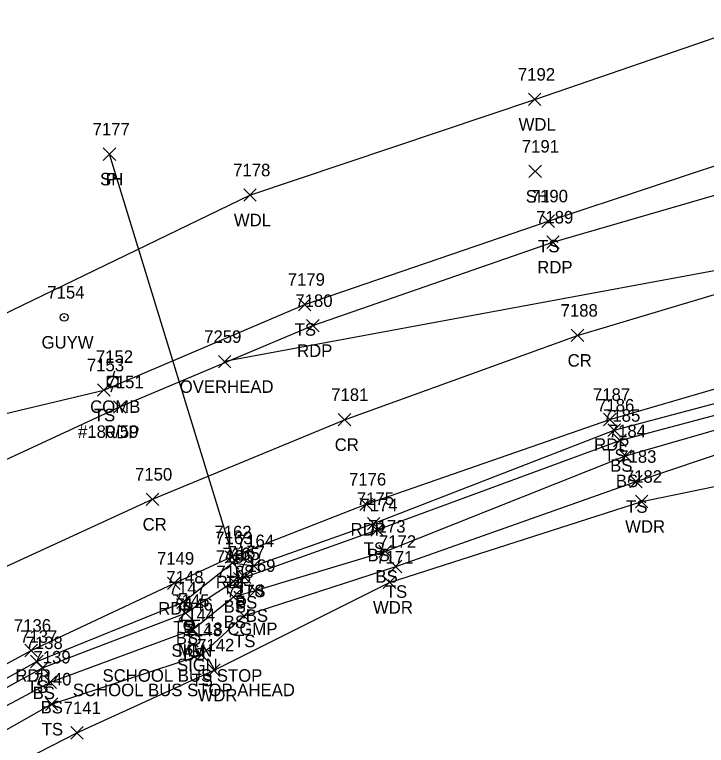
# Model space of a CAD drawing. Extents: x 1611797 to 1633212, y 298978 to 305475.
# Drawn here: x 1624387.7 to 1624498.3, y 304428 to 304544.9 of the extents above; entities that cross this region are included whole.
import ezdxf

# ---------------------------------------------------------------- set-up
doc = ezdxf.new("R2010")
doc.units = 0
for name, color, linetype in [('D_A', 7, 'Continuous'), ('D_C', 7, 'Continuous'), ('D_I', 7, 'Continuous'), ('D_TIC', 7, 'Continuous'), ('DCP', 7, 'Continuous'), ('L_A', 7, 'Continuous'), ('L_I', 7, 'Continuous'), ('L_TIC', 7, 'Continuous'), ('LAWA', 7, 'Continuous'), ('LELB', 7, 'Continuous'), ('P_A', 7, 'Continuous'), ('P_I', 7, 'Continuous'), ('P_TIC', 7, 'Continuous'), ('PET', 7, 'Continuous'), ('PRC', 7, 'Continuous'), ('S_A', 7, 'Continuous'), ('S_C', 7, 'Continuous'), ('S_I', 7, 'Continuous'), ('SRM', 7, 'Continuous'), ('SSGN', 7, 'Continuous'), ('U_A', 7, 'Continuous'), ('U_C', 7, 'Continuous'), ('U_I', 7, 'Continuous'), ('U_TIC', 7, 'Continuous'), ('UCO', 7, 'Continuous'), ('UP', 7, 'Continuous'), ('UPGW', 7, 'Continuous')]:
    doc.layers.add(name, color=color, linetype=linetype)

msp = doc.modelspace()

# ---------------------------------------------------------------- linework, layer by layer
at = {"layer": 'D_TIC'}
for points in [[(1624401.83, 304521.56), (1624403.83, 304523.56)], [(1624403.83, 304521.56), (1624401.83, 304523.56)], [(1624422.66, 304453.61), (1624424.66, 304455.61)], [(1624424.66, 304453.61), (1624422.66, 304455.61)]]:
    msp.add_lwpolyline(points, dxfattribs=at)
at = {"layer": 'DCP'}
msp.add_lwpolyline([(1624423.66, 304454.61), (1624402.83, 304522.56)], dxfattribs=at)
at = {"layer": 'L_TIC'}
for points in [[(1624469.84, 304530.32), (1624471.84, 304532.32)], [(1624471.84, 304530.32), (1624469.84, 304532.32)], [(1624401.83, 304521.56), (1624403.83, 304523.56)], [(1624403.83, 304521.56), (1624401.83, 304523.56)], [(1624469.9, 304518.8), (1624471.9, 304520.8)], [(1624471.9, 304518.8), (1624469.9, 304520.8)], [(1624424.3, 304515.01), (1624426.3, 304517.01)], [(1624426.3, 304515.01), (1624424.3, 304517.01)], [(1624471.98, 304510.84), (1624473.98, 304512.84)], [(1624473.98, 304510.84), (1624471.98, 304512.84)], [(1624433.05, 304497.5), (1624435.05, 304499.5)], [(1624435.05, 304497.5), (1624433.05, 304499.5)], [(1624400.92, 304483.81), (1624402.92, 304485.81)], [(1624402.92, 304483.81), (1624400.92, 304485.81)], [(1624482.55, 304477.38), (1624484.55, 304479.38)], [(1624484.55, 304477.38), (1624482.55, 304479.38)], [(1624483.46, 304475.74), (1624485.46, 304477.74)], [(1624485.46, 304475.74), (1624483.46, 304477.74)], [(1624484.37, 304473.27), (1624486.37, 304475.27)], [(1624486.37, 304473.27), (1624484.37, 304475.27)], [(1624486.04, 304469.17), (1624488.04, 304471.17)], [(1624488.04, 304469.17), (1624486.04, 304471.17)], [(1624486.94, 304465.98), (1624488.94, 304467.98)], [(1624488.94, 304465.98), (1624486.94, 304467.98)], [(1624444.07, 304462.44), (1624446.07, 304464.44)], [(1624446.07, 304462.44), (1624444.07, 304464.44)], [(1624444.65, 304461.42), (1624446.65, 304463.42)], [(1624446.65, 304461.42), (1624444.65, 304463.42)], [(1624445.91, 304458), (1624447.91, 304460)], [(1624447.91, 304458), (1624445.91, 304460)], [(1624421.5, 304456.15), (1624423.5, 304458.15)], [(1624423.5, 304456.15), (1624421.5, 304458.15)], [(1624424.95, 304455.68), (1624426.95, 304457.68)], [(1624426.95, 304455.68), (1624424.95, 304457.68)], [(1624447.61, 304455.57), (1624449.61, 304457.57)], [(1624449.61, 304455.57), (1624447.61, 304457.57)], [(1624423.46, 304453.85), (1624425.46, 304455.85)], [(1624425.46, 304453.85), (1624423.46, 304455.85)], [(1624421.64, 304453.19), (1624423.64, 304455.19)], [(1624423.64, 304453.19), (1624421.64, 304455.19)], [(1624446.61, 304453.04), (1624448.61, 304455.04)], [(1624448.61, 304453.04), (1624446.61, 304455.04)], [(1624425.18, 304451.72), (1624427.18, 304453.72)], [(1624427.18, 304451.72), (1624425.18, 304453.72)], [(1624413.63, 304449.88), (1624415.63, 304451.88)], [(1624415.63, 304449.88), (1624413.63, 304451.88)], [(1624421.67, 304450.72), (1624423.67, 304452.72)], [(1624423.67, 304450.72), (1624421.67, 304452.72)], [(1624414, 304448.13), (1624416, 304450.13)], [(1624416, 304448.13), (1624414, 304450.13)], [(1624423.34, 304447.67), (1624425.34, 304449.67)], [(1624425.34, 304447.67), (1624423.34, 304449.67)], [(1624415.16, 304445.51), (1624417.16, 304447.51)], [(1624417.16, 304445.51), (1624415.16, 304447.51)], [(1624390.23, 304440.37), (1624392.23, 304442.37)], [(1624392.23, 304440.37), (1624390.23, 304442.37)], [(1624416.55, 304441.42), (1624418.55, 304443.42)], [(1624418.55, 304441.42), (1624416.55, 304443.42)], [(1624391.11, 304439.37), (1624393.11, 304441.37)], [(1624393.11, 304439.37), (1624391.11, 304441.37)], [(1624418.55, 304439), (1624420.55, 304441)], [(1624420.55, 304439), (1624418.55, 304441)], [(1624392.38, 304437.07), (1624394.38, 304439.07)], [(1624394.38, 304437.07), (1624392.38, 304439.07)], [(1624392.58, 304433.55), (1624394.58, 304435.55)], [(1624394.58, 304433.55), (1624392.58, 304435.55)], [(1624396.63, 304428.96), (1624398.63, 304430.96)], [(1624398.63, 304428.96), (1624396.63, 304430.96)]]:
    msp.add_lwpolyline(points, dxfattribs=at)
at = {"layer": 'LAWA'}
for points in [[(1624088.25, 304303.5), (1624106.81, 304320.98), (1624153.79, 304356.6), (1624200.5, 304392.1), (1624247.6, 304427), (1624285.25, 304446.91), (1624325.08, 304470.25), (1624369.06, 304488.79), (1624425.3, 304516.01), (1624470.84, 304531.32), (1624503.11, 304542.37)], [(1624186.93, 304294.55), (1624240.75, 304330.36), (1624281.9, 304359.85), (1624320.17, 304387.37), (1624354.03, 304407.62), (1624397.63, 304429.96), (1624419.55, 304440), (1624447.61, 304454.04), (1624487.94, 304466.98), (1624522.27, 304474.07), (1624560.79, 304484.56), (1624594.39, 304487.85), (1624625.21, 304492.09), (1624656.2, 304492.85), (1624695.81, 304490.79), (1624736.39, 304487.29), (1624770.57, 304478.97), (1624808.86, 304473.48), (1624838.37, 304462.56)]]:
    msp.add_lwpolyline(points, dxfattribs=at)
at = {"layer": 'LELB'}
for points in [[(1624095.54, 304298.86), (1624107.13, 304308.7), (1624163.15, 304341.2), (1624211.36, 304376.85), (1624256.11, 304405.01), (1624295.12, 304429.63), (1624332.27, 304455.09), (1624374.78, 304478.34), (1624401.92, 304484.81), (1624434.05, 304498.5), (1624472.98, 304511.84), (1624506.38, 304522.93), (1624552.27, 304533.91), (1624584.91, 304535.68), (1624625.23, 304538.42), (1624653.95, 304544.88), (1624697.41, 304542.2), (1624744.04, 304535.67), (1624782.56, 304529.52), (1624820.4, 304520.29), (1624849.23, 304510.65), (1624882.95, 304501.96), (1624884.04, 304505.26)], [(1624181.13, 304309.78), (1624231.77, 304345.18), (1624273.89, 304372.63), (1624313.92, 304397.95), (1624349.41, 304418.31), (1624391.23, 304441.37), (1624414.63, 304450.88), (1624422.5, 304457.15), (1624425.95, 304456.68), (1624445.07, 304463.44), (1624483.55, 304478.38), (1624517.08, 304487.27), (1624559.27, 304496.93), (1624591.53, 304501.1), (1624624.74, 304505.99)], [(1624181.83, 304308.22), (1624233.12, 304343.37), (1624274.63, 304371.3), (1624314.75, 304397.03), (1624350.32, 304417.49), (1624392.11, 304440.37), (1624415, 304449.13), (1624422.64, 304454.19), (1624424.46, 304454.85), (1624445.65, 304462.42), (1624484.46, 304476.74), (1624518.06, 304485.67), (1624537.67, 304490.32), (1624539.56, 304490.64), (1624559.82, 304495.18), (1624592.05, 304499.97), (1624624.64, 304503.4)], [(1624183.73, 304304.83), (1624234.53, 304340.54), (1624276.44, 304368.9), (1624316.24, 304394.62), (1624351.26, 304415.55), (1624393.38, 304438.07), (1624416.16, 304446.51), (1624422.67, 304451.72), (1624426.18, 304452.72), (1624446.91, 304459), (1624485.37, 304474.27), (1624518.27, 304483.79), (1624538.49, 304488.99), (1624540.45, 304488.77), (1624560, 304493), (1624592, 304498.44), (1624624.83, 304501.63)], [(1624184.93, 304301.87), (1624278.34, 304363.53), (1624318.33, 304391.37), (1624353.31, 304411.71), (1624393.58, 304434.55), (1624417.55, 304442.42), (1624424.34, 304448.67), (1624448.61, 304456.57), (1624487.04, 304470.17), (1624519.68, 304481.19), (1624560.46, 304490.23), (1624593.88, 304492.76), (1624624.32, 304496.68), (1624656.79, 304498.13), (1624695.25, 304497.88), (1624738.57, 304491.31), (1624772.39, 304485.68), (1624810.08, 304476.48), (1624844.46, 304462.44), (1624886.48, 304449.94), (1624926.51, 304437.94), (1624967.18, 304426.7), (1624995.86, 304419.24)]]:
    msp.add_lwpolyline(points, dxfattribs=at)
at = {"layer": 'P_TIC'}
for points in [[(1624472.75, 304507.46), (1624474.75, 304509.46)], [(1624474.75, 304507.46), (1624472.75, 304509.46)], [(1624434.34, 304494.11), (1624436.34, 304496.11)], [(1624436.34, 304494.11), (1624434.34, 304496.11)], [(1624476.67, 304492.55), (1624478.67, 304494.55)], [(1624478.67, 304492.55), (1624476.67, 304494.55)], [(1624403.49, 304481.1), (1624405.49, 304483.1)], [(1624405.49, 304481.1), (1624403.49, 304483.1)], [(1624439.42, 304479.07), (1624441.42, 304481.07)], [(1624441.42, 304479.07), (1624439.42, 304481.07)], [(1624481.84, 304479.09), (1624483.84, 304481.09)], [(1624483.84, 304479.09), (1624481.84, 304481.09)], [(1624408.7, 304466.33), (1624410.7, 304468.33)], [(1624410.7, 304466.33), (1624408.7, 304468.33)], [(1624442.89, 304465.53), (1624444.89, 304467.53)], [(1624444.89, 304465.53), (1624442.89, 304467.53)], [(1624421.35, 304457.1), (1624423.35, 304459.1)], [(1624423.35, 304457.1), (1624421.35, 304459.1)], [(1624412.13, 304452.88), (1624414.13, 304454.88)], [(1624414.13, 304452.88), (1624412.13, 304454.88)], [(1624389.3, 304442.15), (1624391.3, 304444.15)], [(1624391.3, 304442.15), (1624389.3, 304444.15)]]:
    msp.add_lwpolyline(points, dxfattribs=at)
at = {"layer": 'PET'}
for points in [[(1624214.6, 304372.95), (1624258.69, 304401.17), (1624298.33, 304425.53), (1624336.86, 304448), (1624379.58, 304470.59), (1624404.49, 304482.1), (1624435.34, 304495.11), (1624473.75, 304508.46), (1624507.92, 304518.4), (1624553.76, 304528.58), (1624585.04, 304533.35), (1624625.18, 304536.71), (1624654.48, 304537.5), (1624696.33, 304535.75), (1624743.35, 304530.33), (1624780.81, 304524.04), (1624819.04, 304514.44), (1624851.35, 304505.26), (1624901.43, 304489.14), (1624942.08, 304475.33), (1624984.5, 304461.2), (1625019.22, 304449.6)], [(1624179.36, 304312.24), (1624229.96, 304347.62), (1624272.13, 304375.05), (1624312.98, 304399.89), (1624348.37, 304420.48), (1624390.3, 304443.15), (1624413.13, 304453.88), (1624422.35, 304458.1), (1624443.89, 304466.53), (1624482.84, 304480.09), (1624516.09, 304489.8), (1624559.13, 304499.19), (1624590.8, 304503.8), (1624624.98, 304507.12)]]:
    msp.add_lwpolyline(points, dxfattribs=at)
at = {"layer": 'PRC'}
msp.add_lwpolyline([(1624172.24, 304325.39), (1624222.29, 304360.15), (1624264.64, 304387.45), (1624305.78, 304412.86), (1624342.45, 304434.67), (1624384.5, 304455.76), (1624409.7, 304467.33), (1624440.42, 304480.07), (1624477.67, 304493.55), (1624512.04, 304503.84), (1624556.26, 304513.41), (1624588.6, 304518.56), (1624625.39, 304521.45), (1624654.72, 304521.97), (1624694.56, 304520.32), (1624741.33, 304515.35), (1624776.51, 304509.39), (1624814.64, 304500.05), (1624847.34, 304490.65), (1624897.27, 304475.63), (1624938.08, 304462.27), (1624974.99, 304449.94), (1625014.51, 304436.37)], dxfattribs=at)
at = {"layer": 'SRM'}
msp.add_lwpolyline([(1624414.95, 304447.76), (1624416.2, 304447.76), (1624416.2, 304446.51), (1624414.95, 304446.51)], close=True, dxfattribs=at)
msp.add_circle((1624415.57, 304447.14), 0.0833, dxfattribs=at)
at = {"layer": 'SSGN'}
for p, q in [((1624413.95, 304447.99), (1624417.28, 304447.99)), ((1624415.59, 304447.16), (1624415.59, 304447.16)), ((1624414.84, 304445.69), (1624418.17, 304445.69)), ((1624416.48, 304444.85), (1624416.48, 304444.85))]:
    msp.add_line(p, q, dxfattribs=at)
for centre in [(1624415.59, 304447.16), (1624416.48, 304444.85)]:
    msp.add_circle(centre, 0.833, dxfattribs=at)
at = {"layer": 'U_TIC'}
for points in [[(1624420.25, 304488.36), (1624422.25, 304490.36)], [(1624422.25, 304488.36), (1624420.25, 304490.36)]]:
    msp.add_lwpolyline(points, dxfattribs=at)
at = {"layer": 'UCO'}
msp.add_lwpolyline([(1624859.31, 304474.49), (1624700.84, 304542.82), (1624591.7, 304520.94), (1624421.25, 304489.36)], dxfattribs=at)
at = {"layer": 'UP'}
for p, q in [((1624402.52, 304485.33), (1624402.52, 304487)), ((1624402.52, 304487), (1624404.19, 304487)), ((1624403.61, 304487.83), (1624403.36, 304487)), ((1624404.19, 304487), (1624404.19, 304485.33)), ((1624403.36, 304486.16), (1624403.36, 304486.16)), ((1624404.19, 304485.33), (1624402.52, 304485.33)), ((1624403.11, 304484.5), (1624403.36, 304485.33))]:
    msp.add_line(p, q, dxfattribs=at)
msp.add_circle((1624403.36, 304486.16), 0.833, dxfattribs=at)
at = {"layer": 'UPGW'}
for radius in [0.625, 0.0833]:
    msp.add_circle((1624395.58, 304496.45), radius, dxfattribs=at)

# ---------------------------------------------------------------- texts
at = {"layer": 'D_A'}
for p in [(1624402.21, 304517.56), (1624423.04, 304449.61)]:
    msp.add_text('P', height=2, dxfattribs=at).set_placement(p)
at = {"layer": 'D_C'}
msp.add_text('18 CGMP', height=2, dxfattribs=at).set_placement((1624417.95, 304445.61))
at = {"layer": 'D_I'}
for s, p in [('7177', (1624400.14, 304525.56)), ('7165', (1624420.92, 304457.61))]:
    msp.add_text(s, height=2, dxfattribs=at).set_placement(p)
at = {"layer": 'L_A'}
for s, p in [('WDL', (1624468.26, 304526.32)), ('SH', (1624401.32, 304517.56)), ('SH', (1624469.39, 304514.8)), ('WDL', (1624422.72, 304511.01)), ('TS', (1624471.38, 304506.84)), ('TS', (1624432.45, 304493.5)), ('TS', (1624400.33, 304479.81)), ('TS', (1624481.96, 304473.38)), ('BS', (1624482.9, 304471.74)), ('BS', (1624483.81, 304469.27)), ('TS', (1624485.45, 304465.17)), ('WDR', (1624485.3, 304461.98)), ('TS', (1624443.48, 304458.44)), ('BS', (1624444.09, 304457.42)), ('BS', (1624445.36, 304454)), ('TS', (1624420.91, 304452.15)), ('TS', (1624424.36, 304451.68)), ('TS', (1624447.02, 304451.57)), ('BS', (1624422.9, 304449.85)), ('BS', (1624421.08, 304449.19)), ('WDR', (1624444.97, 304449.04)), ('BS', (1624424.62, 304447.72)), ('BS', (1624421.11, 304446.72)), ('TS', (1624413.03, 304445.88)), ('BS', (1624413.44, 304444.13)), ('TS', (1624422.75, 304443.67)), ('BS', (1624414.6, 304441.51)), ('TS', (1624415.96, 304437.42)), ('TS', (1624389.64, 304436.37)), ('BS', (1624390.55, 304435.37)), ('WDR', (1624416.91, 304435)), ('BS', (1624391.82, 304433.07)), ('TS', (1624391.99, 304429.55))]:
    msp.add_text(s, height=2, dxfattribs=at).set_placement(p)
at = {"layer": 'L_I'}
for s, p in [('7192', (1624468.15, 304534.32)), ('7177', (1624400.14, 304525.56)), ('7191', (1624468.77, 304522.8)), ('7178', (1624422.61, 304519.01)), ('7190', (1624470.2, 304514.84)), ('7179', (1624431.34, 304501.5)), ('7153', (1624399.22, 304487.81)), ('7186', (1624480.81, 304481.38)), ('7185', (1624481.77, 304479.74)), ('7184', (1624482.68, 304477.27)), ('7183', (1624484.35, 304473.17)), ('7182', (1624485.25, 304469.98)), ('7175', (1624442.38, 304466.44)), ('7174', (1624442.96, 304465.42)), ('7173', (1624444.22, 304462)), ('7163', (1624419.76, 304460.15)), ('7164', (1624423.21, 304459.68)), ('7172', (1624445.92, 304459.57)), ('7167', (1624421.72, 304457.85)), ('7166', (1624419.85, 304457.19)), ('7171', (1624445.49, 304457.04)), ('7169', (1624423.43, 304455.72)), ('7168', (1624419.93, 304454.72)), ('7148', (1624411.93, 304453.88)), ('7147', (1624412.31, 304452.13)), ('7170', (1624421.56, 304451.67)), ('7146', (1624413.41, 304449.51)), ('7143', (1624414.86, 304445.42)), ('7137', (1624388.54, 304444.37)), ('7138', (1624389.42, 304443.37)), ('7142', (1624416.85, 304443)), ('7139', (1624390.68, 304441.07)), ('7140', (1624390.8, 304437.55)), ('7141', (1624395.51, 304432.96))]:
    msp.add_text(s, height=2, dxfattribs=at).set_placement(p)
at = {"layer": 'P_A'}
for s, p in [('RDP', (1624471.24, 304503.46)), ('RDP', (1624432.83, 304490.11)), ('CR', (1624476.1, 304488.55)), ('RDP', (1624401.98, 304477.1)), ('CR', (1624438.85, 304475.07)), ('RDP', (1624480.33, 304475.09)), ('CR', (1624408.13, 304462.33)), ('RDP', (1624441.38, 304461.53)), ('RDP', (1624419.84, 304453.1)), ('RDP', (1624410.62, 304448.88)), ('RDP', (1624387.78, 304438.15))]:
    msp.add_text(s, height=2, dxfattribs=at).set_placement(p)
at = {"layer": 'P_I'}
for s, p in [('7189', (1624471.05, 304511.46)), ('7180', (1624432.56, 304498.11)), ('7188', (1624474.98, 304496.55)), ('7151', (1624402.36, 304485.1)), ('7181', (1624438.29, 304483.07)), ('7187', (1624480.15, 304483.09)), ('7150', (1624406.92, 304470.33)), ('7176', (1624441.14, 304469.53)), ('7162', (1624419.61, 304461.1)), ('7149', (1624410.43, 304456.88)), ('7136', (1624387.55, 304446.15))]:
    msp.add_text(s, height=2, dxfattribs=at).set_placement(p)
at = {"layer": 'S_A'}
for s, p in [('SIGN', (1624412.73, 304442.14)), ('MM', (1624413.76, 304442.14)), ('SIGN', (1624413.62, 304439.83))]:
    msp.add_text(s, height=2, dxfattribs=at).set_placement(p)
at = {"layer": 'S_C'}
for s, p in [('SCHOOL BUS STOP', (1624401.72, 304438.14)), ('SCHOOL BUS STOP AHEAD', (1624396.97, 304435.83))]:
    msp.add_text(s, height=2, dxfattribs=at).set_placement(p)
at = {"layer": 'S_I'}
for s, p in [('7145', (1624412.88, 304450.14)), ('7145', (1624412.88, 304450.14)), ('7144', (1624413.77, 304447.83))]:
    msp.add_text(s, height=2, dxfattribs=at).set_placement(p)
at = {"layer": 'U_A'}
for s, p in [('GUYW', (1624391.97, 304491.45)), ('OVERHEAD', (1624414.06, 304484.36)), ('COMB', (1624399.74, 304481.16))]:
    msp.add_text(s, height=2, dxfattribs=at).set_placement(p)
at = {"layer": 'U_C'}
msp.add_text('#180/59', height=2, dxfattribs=at).set_placement((1624397.8, 304477.16))
at = {"layer": 'U_I'}
for s, p in [('7154', (1624392.89, 304499.45)), ('7259', (1624417.98, 304492.36)), ('7152', (1624400.66, 304489.16))]:
    msp.add_text(s, height=2, dxfattribs=at).set_placement(p)

doc.saveas('drawing.dxf')
